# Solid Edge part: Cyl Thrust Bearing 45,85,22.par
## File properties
Author: Dan
Template: Normal.par
Last saved by: Dan
Revision: 1
Application: Solid Edge
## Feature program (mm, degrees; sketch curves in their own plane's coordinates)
sketch for "unnamed Protrusion 1" #1 plane through (0, 0, 0) normal (0, 0, 1) x-axis (1, 0, 0)
  circle centre (0, 0) radius 22.5
sketch for "unnamed Protrusion 1" #2 plane through (0, 0, 0) normal (0, 0, 1) x-axis (1, 0, 0)
  circle centre (0, 0) radius 42.5
extrude "unnamed Protrusion 1" add finite 22 along +normal
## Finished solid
Body 1: solid body, 4 faces, 4 edges, 0 vertices.
  Faces by surface: cylinder 2, plane 2
  Edges by curve: circle 4
Bounding box of the edges (mm): 85.000 x 85.000 x 22.000, from (-42.5, -42.5, 0) to (42.5, 42.5, 22).
Cylindrical faces by radius (mm): R22.5 x1, R42.5 x1
Planar faces by outward normal: +z 1, -z 1
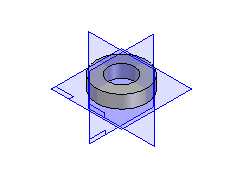
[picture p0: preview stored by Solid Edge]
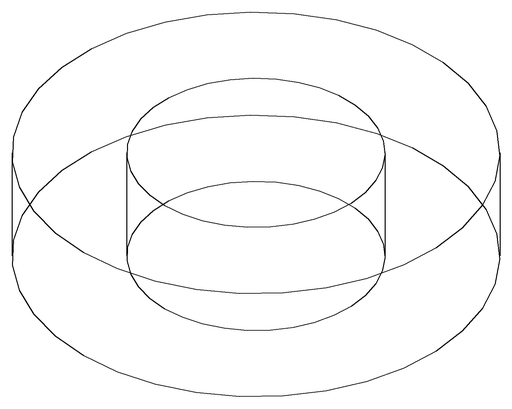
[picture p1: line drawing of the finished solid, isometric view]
